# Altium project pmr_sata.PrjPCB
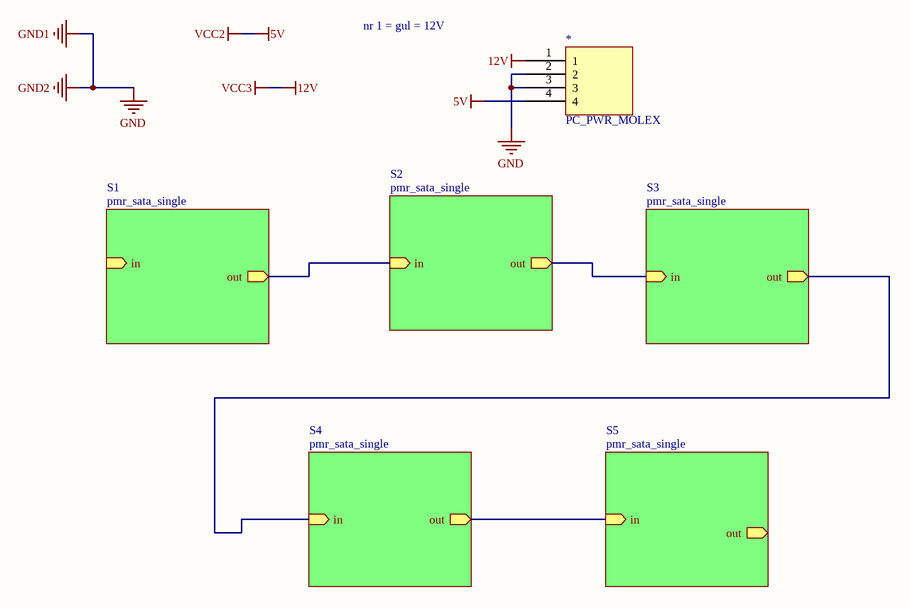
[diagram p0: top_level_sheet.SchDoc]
2 sheets, 11 parts. Net scope: hierarchical (ports join the sheet entries above them; power ports are global).
Board file: pmr_sata7.PcbDoc
Sheets:
  top_level_sheet.SchDoc
    S1 = pmr_sata_single.SchDoc
    S2 = pmr_sata_single.SchDoc
    S3 = pmr_sata_single.SchDoc
    S4 = pmr_sata_single.SchDoc
    S5 = pmr_sata_single.SchDoc

## Sheet top_level_sheet.SchDoc
size A4

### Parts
*  PC_PWR_MOLEX  [PC_PWR_MOLEX]

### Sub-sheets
S1 = pmr_sata_single: in (in), out (out)
S2 = pmr_sata_single: out (out), in (in)
S3 = pmr_sata_single: out (out), in (in)
S4 = pmr_sata_single: out (out), in (in)
S5 = pmr_sata_single: out (out), in (in)

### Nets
5V: *.4  [also labelled VCC2]
12V: *.1  [also labelled VCC3]
GND: *.2 *.3  [also labelled GND1, GND2]
(unnamed): sheet S1/out, sheet S2/in
(unnamed): sheet S2/out, sheet S3/in  [a separate net that carries the same name]
(unnamed): sheet S3/out, sheet S4/in  [a separate net that carries the same name]
(unnamed): sheet S4/out, sheet S5/in  [a separate net that carries the same name]

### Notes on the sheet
- nr 1 = gul = 12V

## Sheet pmr_sata_single.SchDoc
size A4
Used 5 times, as channels S1, S2, S3, S4, S5. Parts and nets are listed once, with the designators drawn on the sheet.
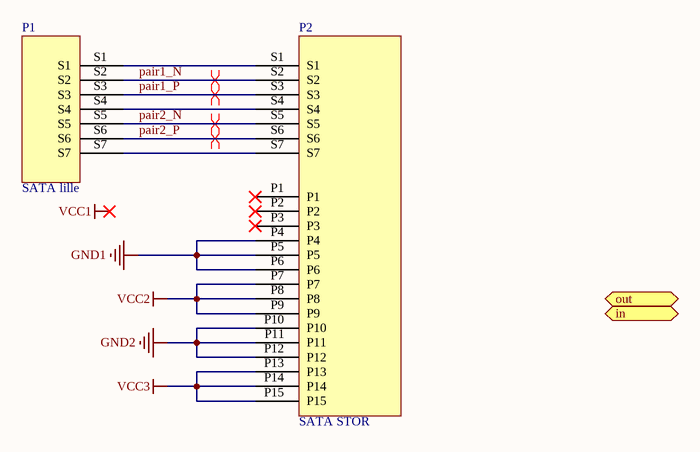
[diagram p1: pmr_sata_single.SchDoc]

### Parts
P1  SATA lille  [pmr_sata -lille ny]
P2  SATA STOR  [pmr_sata]

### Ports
in (in), out (out)

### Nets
GND1: P2.P4 P2.P5 P2.P6
GND2: P2.P10 P2.P11 P2.P12
VCC2: P2.P7 P2.P8 P2.P9
VCC3: P2.P13 P2.P14 P2.P15
pair1_N: P1.S2 P2.S2
pair1_P: P1.S3 P2.S3
pair2_N: P1.S5 P2.S5
pair2_P: P1.S6 P2.S6
NetP1_S1: P1.S1 P2.S1
NetP1_S4: P1.S4 P2.S4
NetP1_S7: P1.S7 P2.S7

Not connected (* = marked no-connect by the designer): P2 P1* P2* P3*

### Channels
S1: designators end in _S1; ports in=open out=open
S2: designators end in _S2; ports in=open out=open
S3: designators end in _S3; ports in=open out=open
S4: designators end in _S4; ports in=open out=open
S5: designators end in _S5; ports in=open out=open

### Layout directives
differential pair: pair1_N_S1, pair1_P_S1, pair2_N_S1, pair2_P_S1

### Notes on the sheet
- Labels drawn without touching a wire or pin: VCC1

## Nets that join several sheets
5V: top_level_sheet (*.4), S1 (P2_S1.P7 P2_S1.P8 P2_S1.P9), S2 (P2_S2.P7 P2_S2.P8 P2_S2.P9), S3 (P2_S3.P7 P2_S3.P8 P2_S3.P9), S4 (P2_S4.P7 P2_S4.P8 P2_S4.P9), S5 (P2_S5.P7 P2_S5.P8 P2_S5.P9)
12V: top_level_sheet (*.1), S1 (P2_S1.P13 P2_S1.P14 P2_S1.P15), S2 (P2_S2.P13 P2_S2.P14 P2_S2.P15), S3 (P2_S3.P13 P2_S3.P14 P2_S3.P15), S4 (P2_S4.P13 P2_S4.P14 P2_S4.P15), S5 (P2_S5.P13 P2_S5.P14 P2_S5.P15)
GND: top_level_sheet (*.2 *.3), S1 (6 pins), S2 (6 pins), S3 (6 pins), S4 (6 pins), S5 (6 pins)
